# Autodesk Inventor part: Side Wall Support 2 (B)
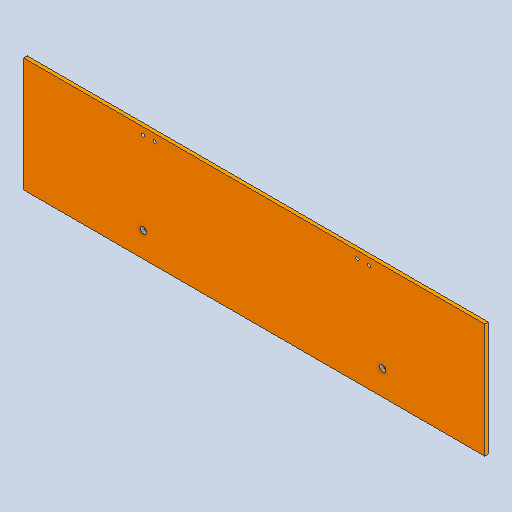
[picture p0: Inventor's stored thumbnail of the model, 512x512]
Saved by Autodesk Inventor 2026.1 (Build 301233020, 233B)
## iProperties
Created: 2026-11
Part Number: Side Wall Support 2 (B)
Material: Generic
Document SubType Name: Modeling
Designer: hp
Density: 1 g/cm^3
Appearance: Default
Author: hp
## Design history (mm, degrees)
sketch "Sketch1"
  geometry: L1 (0, 0)-(645, 0); L2 (645, 0)-(645, 160); L3 (645, 160)-(0, 160); L4 (0, 160)-(0, 0)
  constraints: 8 end point, 2 parallel, 1 horizontal, 1 perpendicular
  dimensions: "d0" = 645 distance of L3.end L2.end; "d1" = 160 distance of L2.end L1.end
extrude "Extrusion1" new body sketch "Sketch1" distance "d2" = 5; taper "d3" = 0 deg
sketch "Sketch2"
  geometry: 4 further points
hole "Hole1" sketch "Sketch2" at (-483, 150), (-467, 150), (-183, 150), (-167, 150) diameter "d4" = 4.5; stored, may be unused: countersink angle "d8" = 90 deg, drill point angle "d10" = 0 deg; dims "d5" = 6, "d6" = 4, "d7" = 2, "d9" = 8
sketch "Sketch3"
  geometry: 2 further points
hole "Hole2" sketch "Sketch3" at (502.5, 35), (167.5, 35) diameter "d11" = 9; stored, may be unused: countersink angle "d15" = 90 deg, drill point angle "d17" = 0 deg; dims "d12" = 6, "d13" = 4, "d14" = 2, "d16" = 8
body "Solid1"
